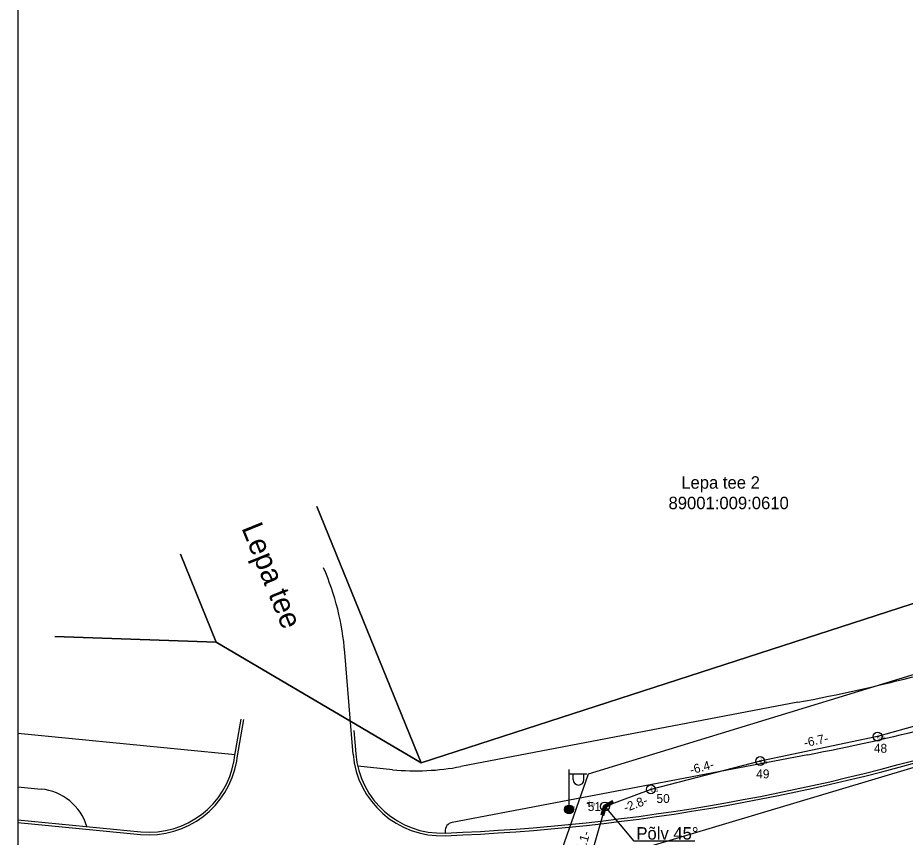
# Model space of a CAD drawing. Extents: x 546339 to 546593, y 6597108 to 6597251.
# Drawn here: x 546339.38 to 546389.31, y 6597156.24 to 6597202.36 of the extents above; entities that cross this region are included whole.
import ezdxf

# ---------------------------------------------------------------- set-up
doc = ezdxf.new("R2010")
doc.units = 0
for name, color, linetype in [('JOONSIDE', 7, 'Continuous'), ('KOORDPUNKT', 7, 'Continuous'), ('MOOTKORG-EH2000', 7, 'Continuous'), ('MOOTMPUNKT', 7, 'Continuous'), ('MOOTNR', 7, 'Continuous'), ('MOOTPIIR', 7, 'Continuous'), ('PIIR', 7, 'Continuous'), ('POST', 7, 'Continuous'), ('SITRASS', 7, 'Continuous'), ('TEE', 7, 'Continuous'), ('VORMISTUS', 7, 'Continuous')]:
    doc.layers.add(name, color=color, linetype=linetype)

msp = doc.modelspace()

# ---------------------------------------------------------------- linework, layer by layer
at = {"layer": 'KOORDPUNKT'}
for centre, radius in [((546387.753, 6597161.903), 0.25), ((546387.753, 6597161.903), 0.025), ((546387.753, 6597161.903), 0.0221), ((546387.753, 6597161.903), 0.0191), ((546387.753, 6597161.903), 0.0161), ((546387.753, 6597161.903), 0.0132), ((546387.753, 6597161.903), 0.0102), ((546387.753, 6597161.903), 0.00726), ((546387.753, 6597161.903), 0.0043), ((546381.148, 6597160.525), 0.25), ((546381.148, 6597160.525), 0.025), ((546381.148, 6597160.525), 0.0221), ((546381.148, 6597160.525), 0.0191), ((546381.148, 6597160.525), 0.0161), ((546381.148, 6597160.525), 0.0132), ((546381.148, 6597160.525), 0.0102), ((546381.148, 6597160.525), 0.00726), ((546381.148, 6597160.525), 0.0043), ((546374.997, 6597158.932), 0.25), ((546374.997, 6597158.932), 0.025), ((546374.997, 6597158.932), 0.0221), ((546374.997, 6597158.932), 0.0191), ((546374.997, 6597158.932), 0.0161), ((546374.997, 6597158.932), 0.0132), ((546374.997, 6597158.932), 0.0102), ((546374.997, 6597158.932), 0.00726), ((546374.997, 6597158.932), 0.0043), ((546372.419, 6597157.971), 0.25), ((546372.419, 6597157.971), 0.025), ((546372.419, 6597157.971), 0.0221), ((546372.419, 6597157.971), 0.0191), ((546372.419, 6597157.971), 0.0161), ((546372.419, 6597157.971), 0.0132), ((546372.419, 6597157.971), 0.0102), ((546372.419, 6597157.971), 0.00726), ((546372.419, 6597157.971), 0.0043)]:
    msp.add_circle(centre, radius, dxfattribs=at)
at = {"layer": 'MOOTMPUNKT'}
for centre in [(546387.753, 6597161.903), (546381.148, 6597160.525), (546374.997, 6597158.932), (546371.459, 6597158.161), (546370.396, 6597157.802)]:
    msp.add_circle(centre, 0.03, dxfattribs=at)
at = {"layer": 'MOOTPIIR'}
msp.add_lwpolyline([(546443.888, 6597176.348), (546374.62, 6597155.63), (546372.739, 6597147.606), (546361.644, 6597146.697), (546361.895, 6597151.274), (546368.79, 6597152.088), (546371.486, 6597159.799), (546428.467, 6597177.226), (546428.906, 6597181.927), (546431.038, 6597182.742), (546435.363, 6597179.169)], dxfattribs=at)
at = {"layer": 'PIIR'}
for points in [[(546510.07, 6597205.36), (546491.04, 6597199.45), (546466.79, 6597191.98), (546431.99, 6597181.07), (546399.93, 6597171.7), (546399.49, 6597172.55), (546362.07, 6597160.42), (546350.54, 6597167.22), (546341.457, 6597167.537)], [(546356.198, 6597174.862), (546362.07, 6597160.42), (546399.49, 6597172.55), (546392.84, 6597188.911)], [(546348.534, 6597172.169), (546350.54, 6597167.22), (546362.07, 6597160.42), (546356.198, 6597174.862)], [(546341.457, 6597167.537), (546350.54, 6597167.22), (546348.534, 6597172.169)]]:
    msp.add_lwpolyline(points, dxfattribs=at)
at = {"layer": 'POST'}
for p, q in [((546370.396, 6597158.052), (546370.396, 6597160.052)), ((546370.396, 6597159.802), (546371.396, 6597159.802)), ((546370.623, 6597159.481), (546370.623, 6597159.802)), ((546371.235, 6597159.481), (546371.235, 6597159.802)), ((546370.396, 6597157.802), (546370.396, 6597157.802))]:
    msp.add_line(p, q, dxfattribs=at)
for radius in [0.25, 0.225, 0.2, 0.175, 0.15, 0.125, 0.1, 0.075, 0.05, 0.025]:
    msp.add_circle((546370.396, 6597157.802), radius, dxfattribs=at)
msp.add_arc((546370.929, 6597159.481), 0.306, 180, 0, dxfattribs=at)
at = {"layer": 'SITRASS'}
for p, q in [((546372.819, 6597158.28), (546372.355, 6597158.021)), ((546372.856, 6597158.215), (546372.419, 6597157.971)), ((546372.712, 6597158.049), (546372.647, 6597158.184)), ((546372.734, 6597158.061), (546372.669, 6597158.196)), ((546372.756, 6597158.073), (546372.691, 6597158.209)), ((546372.778, 6597158.085), (546372.713, 6597158.221)), ((546372.8, 6597158.098), (546372.734, 6597158.233)), ((546372.822, 6597158.11), (546372.756, 6597158.245)), ((546372.844, 6597158.122), (546372.778, 6597158.257)), ((546372.865, 6597158.134), (546372.8, 6597158.27)), ((546372.892, 6597158.149), (546372.819, 6597158.28)), ((546372.887, 6597158.147), (546372.845, 6597158.234)), ((546372.211, 6597157.51), (546372.355, 6597158.021)), ((546372.365, 6597157.504), (546372.267, 6597157.707)), ((546372.375, 6597157.54), (546372.277, 6597157.743)), ((546372.283, 6597157.49), (546372.419, 6597157.971)), ((546372.385, 6597157.576), (546372.287, 6597157.78)), ((546372.396, 6597157.612), (546372.297, 6597157.816)), ((546372.406, 6597157.649), (546372.308, 6597157.852)), ((546372.416, 6597157.685), (546372.318, 6597157.888)), ((546372.426, 6597157.721), (546372.328, 6597157.925)), ((546372.437, 6597157.757), (546372.338, 6597157.961)), ((546372.447, 6597157.794), (546372.349, 6597157.997)), ((546372.355, 6597157.469), (546372.483, 6597157.921)), ((546372.457, 6597157.83), (546372.363, 6597158.025)), ((546372.467, 6597157.866), (546372.385, 6597158.037)), ((546372.478, 6597157.902), (546372.406, 6597158.05)), ((546372.494, 6597157.927), (546372.428, 6597158.062)), ((546372.516, 6597157.939), (546372.45, 6597158.074)), ((546372.537, 6597157.951), (546372.472, 6597158.086)), ((546372.892, 6597158.149), (546372.483, 6597157.921)), ((546372.559, 6597157.963), (546372.494, 6597158.099)), ((546372.581, 6597157.975), (546372.516, 6597158.111)), ((546372.603, 6597157.988), (546372.538, 6597158.123)), ((546372.625, 6597158), (546372.559, 6597158.135)), ((546372.647, 6597158.012), (546372.581, 6597158.147)), ((546372.669, 6597158.024), (546372.603, 6597158.16)), ((546372.69, 6597158.037), (546372.625, 6597158.172)), ((546372.355, 6597157.469), (546372.211, 6597157.51)), ((546372.225, 6597157.506), (546372.215, 6597157.526)), ((546372.257, 6597157.497), (546372.226, 6597157.562)), ((546372.289, 6597157.488), (546372.236, 6597157.598)), ((546372.321, 6597157.479), (546372.246, 6597157.635)), ((546372.353, 6597157.47), (546372.256, 6597157.671))]:
    msp.add_line(p, q, dxfattribs=at)
for points in [[(546412.984, 6597169.682), (546404.421, 6597166.986), (546400.555, 6597165.683), (546393.387, 6597163.477), (546387.753, 6597161.903), (546381.148, 6597160.525), (546374.997, 6597158.932), (546372.419, 6597157.971), (546371.306, 6597154.04), (546370.157, 6597150.238), (546369.857, 6597149.704), (546369.198, 6597149.563), (546364.495, 6597149.159), (546363.925, 6597149.09)], [(546377.463, 6597156.009), (546374.06, 6597156.009), (546372.419, 6597157.971)]]:
    msp.add_lwpolyline(points, dxfattribs=at)
at = {"layer": 'TEE'}
for p, q in [((546356.583, 6597171.405), (546356.583, 6597171.405)), ((546351.582, 6597160.74), (546351.953, 6597162.892)), ((546351.73, 6597160.714), (546352.101, 6597162.867)), ((546358.246, 6597160.914), (546358.137, 6597162.254)), ((546358.288, 6597162.249), (546358.395, 6597160.926)), ((546351.55, 6597160.553), (546351.582, 6597160.74)), ((546360.47, 6597160.042), (546358.503, 6597160.233)), ((546339.379, 6597157.072), (546346.286, 6597156.4)), ((546343.269, 6597156.844), (546343.269, 6597156.844)), ((546363.417, 6597156.561), (546363.42, 6597156.474))]:
    msp.add_line(p, q, dxfattribs=at)
for points in [[(546358.137, 6597162.254), (546357.78, 6597166.638), (546357.78, 6597166.638)], [(546383.275, 6597163.832), (546383.275, 6597163.832), (546364.306, 6597160.217)], [(546339.379, 6597162.096), (546351.611, 6597160.905)], [(546351.698, 6597160.528), (546351.698, 6597160.528), (546351.73, 6597160.714)], [(546383.837, 6597160.885), (546383.837, 6597160.885), (546363.823, 6597157.071)], [(546339.379, 6597159.082), (546340.691, 6597158.954)], [(546339.379, 6597157.223), (546346.301, 6597156.549)]]:
    msp.add_lwpolyline(points, dxfattribs=at)
for centre, radius, start, end in [((546342.829, 6597165.42), 15, 4.6585, 23.5163), ((546362.026, 6597275.325), 113.5, 280.79026, 287.8433), ((546362.026, 6597275.325), 116.5, 280.79026, 287.8433), ((546358.831, 6597273.234), 116.85, 272.25054, 287.8487), ((546358.831, 6597273.234), 117, 272.25054, 287.8487), ((546363.229, 6597161.32), 5, 184.6585, 272.2505), ((546363.229, 6597161.32), 4.85, 184.6585, 272.2505), ((546346.771, 6597161.376), 5, 264.437, 350.2348), ((546346.771, 6597161.376), 4.85, 264.437, 350.2348), ((546361.779, 6597173.478), 13.5, 264.437, 280.7903), ((546340.4, 6597155.968), 3, 16.9773, 84.437), ((546363.917, 6597156.58), 0.5, 100.7903, 182.1253)]:
    msp.add_arc(centre, radius, start, end, dxfattribs=at)
at = {"layer": 'VORMISTUS'}
msp.add_lwpolyline([(546593.177, 6597250.72), (546339.379, 6597250.72), (546339.379, 6597108.37), (546593.177, 6597108.37)], close=True, dxfattribs=at)

# ---------------------------------------------------------------- texts
at = {"layer": 'JOONSIDE'}
for s, rotation, p in [('-6.7-', 11.7841, (546383.665, 6597161.305)), ('-6.4-', 14.5238, (546377.26, 6597159.776)), ('-2.8-', 20.4375, (546373.571, 6597157.644)), ('-4.1-', 74.1952, (546371.221, 6597155.188))]:
    msp.add_text(s, height=0.5, rotation=rotation, dxfattribs=at).set_placement(p)
at = {"layer": 'KOORDPUNKT'}
for s, p in [('48', (546387.546, 6597160.996)), ('49', (546380.925, 6597159.554)), ('50', (546375.315, 6597158.168)), ('51', (546371.448, 6597157.716))]:
    msp.add_text(s, height=0.5, dxfattribs=at).set_placement(p)
at = {"layer": 'MOOTKORG-EH2000'}
for s, p in [('6.09', (546387.753, 6597161.753)), ('6.19', (546381.148, 6597160.375)), ('6.13', (546374.997, 6597158.782)), ('7.11', (546370.396, 6597157.652)), ('6.00', (546371.459, 6597158.011))]:
    msp.add_text(s, height=0.15, dxfattribs=at).set_placement(p)
at = {"layer": 'MOOTNR'}
for s, p in [('1', (546387.753, 6597161.903)), ('1', (546381.148, 6597160.525)), ('1', (546374.997, 6597158.932)), ('1', (546371.459, 6597158.161)), ('157', (546370.396, 6597157.802))]:
    msp.add_text(s, height=0.15, dxfattribs=at).set_placement(p)
at = {"layer": 'PIIR'}
for s, p in [('Lepa tee 2', (546376.708, 6597175.855)), ('89001:009:0610', (546375.991, 6597174.702))]:
    msp.add_text(s, height=0.7, dxfattribs=at).set_placement(p)
at = {"layer": 'SITRASS'}
msp.add_text('Põlv 45°', height=0.7, dxfattribs=at).set_placement((546374.183, 6597156.107))
at = {"layer": 'TEE'}
msp.add_text('Lepa tee', height=1.2, rotation=292.0673, dxfattribs=at).set_placement((546351.952, 6597173.646))

doc.saveas('drawing.dxf')
